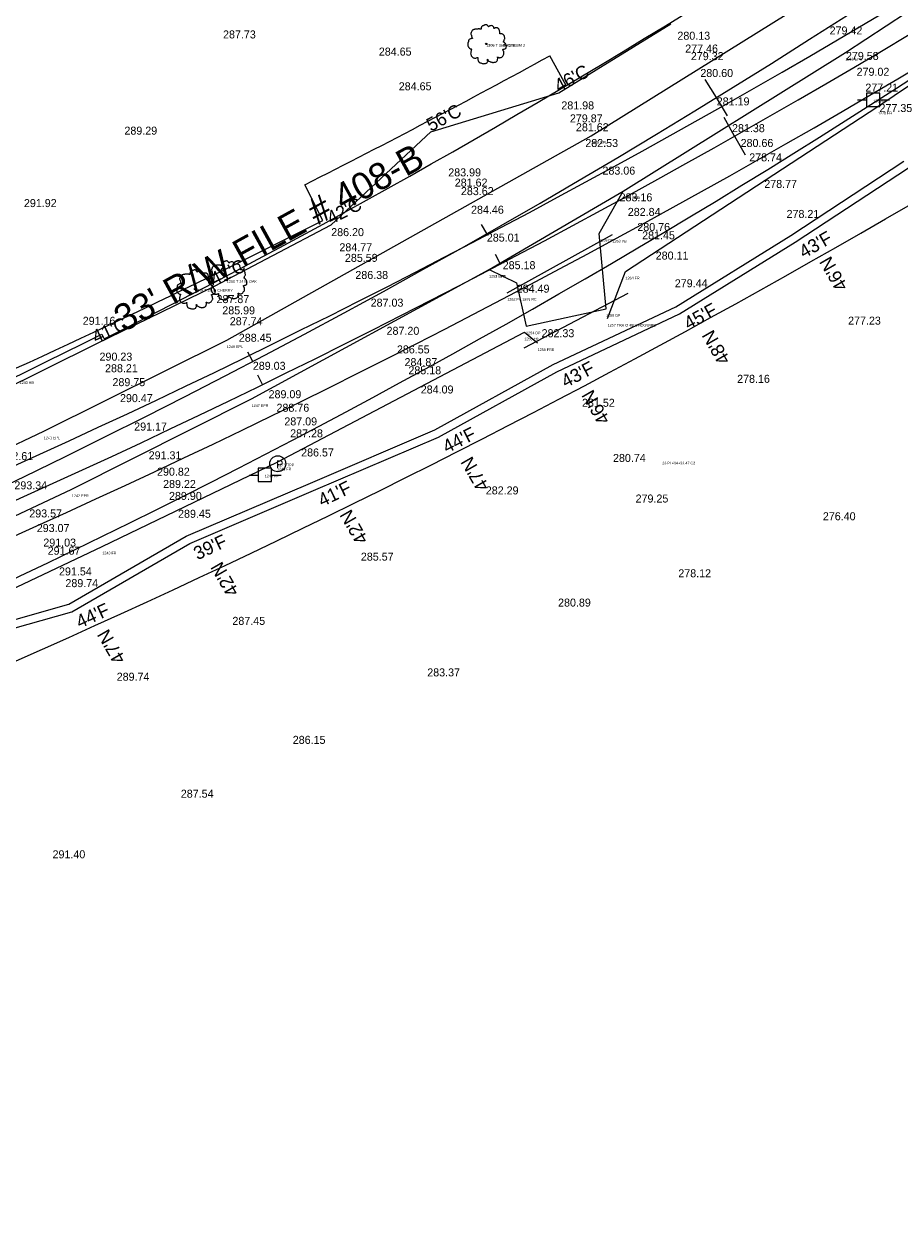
# Model space of a CAD drawing. Extents: x 49683 to 58852, y 49525 to 54803.
# Drawn here: x 51884.7 to 52213, y 49959.7 to 50412.9 of the extents above; entities that cross this region are included whole.
import ezdxf

# ---------------------------------------------------------------- set-up
doc = ezdxf.new("R2010")
doc.units = 0
for name, color, linetype in [('Level 1', 7, 'Continuous'), ('Level 11', 7, 'Continuous'), ('Level 13', 7, 'Continuous'), ('Level 18', 7, 'Continuous'), ('Level 19', 7, 'Continuous'), ('Level 20', 7, 'Continuous'), ('Level 25', 7, 'Continuous'), ('Level 3', 7, 'Continuous'), ('Level 32', 7, 'Continuous'), ('Level 33', 7, 'Continuous'), ('Level 34', 7, 'Continuous'), ('Level 48', 7, 'Continuous'), ('Level 51', 7, 'Continuous'), ('Level 53', 7, 'Continuous'), ('Level 56', 7, 'Continuous'), ('Level 58', 7, 'Continuous'), ('Level 59', 7, 'Continuous'), ('Level 6', 7, 'Continuous'), ('Level 61', 7, 'Continuous'), ('Level 8', 7, 'Continuous'), ('Level 9', 7, 'Continuous')]:
    doc.layers.add(name, color=color, linetype=linetype)

# ---------------------------------------------------------------- blocks, each defined once
blk = doc.blocks.new('PP')
at = {"layer": 'Level 9'}
for p, q in [((2.53, 2.45), (-2.47, 2.45)), ((-2.47, 2.45), (-2.47, -2.55)), ((2.53, -2.55), (2.53, 2.45)), ((-5.91, -0.11), (-2.44, -0.11)), ((-2.47, -2.55), (2.53, -2.55)), ((2.45, -0.11), (6.09, -0.11))]:
    blk.add_line(p, q, dxfattribs=at)
blk = doc.blocks.new('TPP')
at = {"layer": 'Level 9'}
blk.add_circle((0, 0), 3, dxfattribs=at)
blk.add_text('P', height=3, dxfattribs=at).set_placement((-0.59, -1.73))
blk = doc.blocks.new('T1')
at = {"layer": 'Level 11'}
for centre, radius in [((0, 0), 0.25), ((-0.01, -0.02), 0.0001)]:
    blk.add_circle(centre, radius, dxfattribs=at)
for points in [[(0.13, 7.17), (-0.17, 7.19), (-0.49, 7.09), (-0.74, 6.99), (-0.97, 6.92), (-1.19, 6.82), (-1.49, 6.64), (-1.72, 6.44), (-1.84, 6.19), (-1.89, 5.97), (-1.94, 5.69), (-1.94, 5.52), (-2.07, 5.49), (-2.22, 5.52), (-2.47, 5.59), (-2.72, 5.59), (-2.97, 5.59), (-3.32, 5.57), (-3.67, 5.57), (-3.94, 5.52), (-4.27, 5.47), (-4.64, 5.34), (-4.99, 5.22), (-5.29, 4.97), (-5.54, 4.49), (-5.67, 4.14), (-5.82, 3.89), (-5.67, 3.44), (-5.49, 3.09), (-5.47, 2.89), (-5.39, 2.47), (-5.29, 2.24), (-5.17, 2.04), (-5.24, 2.02), (-5.62, 1.97), (-5.92, 1.87), (-6.34, 1.64), (-6.57, 1.42), (-6.67, 1.09), (-6.69, 0.75), (-6.79, 0.55), (-6.87, 0.27), (-6.89, 0.2), (-6.94, -0.13), (-6.84, -0.58), (-6.82, -0.93), (-6.69, -1.15), (-6.54, -1.33), (-6.37, -1.58), (-5.97, -1.8), (-5.64, -1.9), (-5.44, -1.93), (-5.62, -2.43), (-5.67, -2.78), (-5.79, -3.18), (-5.79, -3.25), (-5.84, -3.73), (-5.69, -4.05), (-5.62, -4.43), (-5.44, -4.65), (-5.17, -4.95), (-4.84, -5.18), (-4.34, -5.3), (-3.94, -5.28), (-3.37, -5.1), (-3.12, -5.03), (-3.14, -5.2), (-3.12, -5.58), (-3.12, -6), (-2.97, -6.33), (-2.87, -6.6), (-2.72, -6.85), (-2.39, -7.08), (-1.99, -7.15), (-1.57, -7.3), (-1.12, -7.38), (-0.62, -7.4), (-0.02, -7.25), (0.26, -7.13), (0.36, -6.95), (0.56, -6.58), (0.51, -6.35), (0.53, -5.75), (0.63, -5.93), (0.81, -6.28), (1.31, -6.58), (1.71, -6.75), (2.18, -6.9), (2.48, -6.98), (2.96, -6.9), (3.33, -6.83), (3.71, -6.7), (4.01, -6.43), (4.18, -6.15), (4.23, -5.88), (4.31, -5.5), (4.36, -5.33)], [(4.36, -5.33), (4.28, -5.15), (4.23, -4.9), (4.31, -4.93), (4.48, -4.98), (4.75, -5.1), (4.98, -5.18), (5.3, -5.15), (5.58, -5.05), (6.03, -4.78), (6.3, -4.3), (6.58, -3.9), (6.65, -3.58), (6.6, -3.35), (6.58, -2.85), (6.38, -2.6), (6.33, -2.48), (6.23, -2.08), (6.3, -2.03), (6.58, -1.98), (6.95, -1.85), (7.23, -1.73), (7.45, -1.55), (7.53, -1.33), (7.5, -0.93), (7.55, -0.53), (7.48, -0.38), (7.38, -0.23), (7.3, -0.03), (7.15, 0.12), (7.05, 0.27), (6.95, 0.37), (6.83, 0.52), (6.65, 0.65), (6.5, 0.7), (6.45, 0.85), (6.6, 1.04), (6.65, 1.14), (6.68, 1.37), (6.9, 1.72), (6.95, 2.12), (6.9, 2.54), (6.85, 2.82), (6.7, 3.09), (6.5, 3.34), (6.38, 3.52), (6.2, 3.64), (5.88, 3.77), (5.63, 3.82), (5.28, 3.82), (5.08, 3.87), (5.1, 3.92), (5.1, 4.07), (5.1, 4.34), (5.03, 4.79), (4.88, 5.29), (4.88, 5.32), (4.78, 5.57), (4.56, 5.77), (4.38, 5.87), (4.18, 5.99), (3.93, 6.02), (3.63, 6.02), (3.36, 5.97), (3.16, 5.87), (2.98, 5.74), (2.91, 5.89), (2.81, 6.19), (2.76, 6.34), (2.61, 6.52), (2.38, 6.72), (1.93, 6.84), (1.31, 6.77), (1.01, 6.57), (0.86, 6.39), (0.81, 6.52), (0.61, 6.72), (0.51, 6.89), (0.33, 7.02), (0.18, 7.12), (0.08, 7.17)]]:
    blk.add_spline(points, degree=3, dxfattribs=at)

msp = doc.modelspace()

# ---------------------------------------------------------------- linework, layer by layer
at = {"layer": 'Level 1'}
for p, q in [((52144.23, 50385.43), (52140.03, 50392.24)), ((52148.42, 50378.61), (52144.23, 50385.43)), ((52058.19, 50334.47), (52056.21, 50337.95)), ((51970.43, 50286.55), (51968.57, 50290.09))]:
    msp.add_line(p, q, dxfattribs=at)
msp.add_arc((50641.56, 52824.47), 2864.78, 268.37962, 311.63333, dxfattribs=at)
at = {"layer": 'Level 13'}
msp.add_line((51913.82, 50296.82), (51914.71, 50295.04), dxfattribs=at)
for radius, start, end in [(2897.79, 282.71776, 311.63339), (2831.79, 296.71776, 308.71775), (2829.79, 291.71776, 296.71776)]:
    msp.add_arc((50641.55, 52824.48), radius, start, end, dxfattribs=at)
at = {"layer": 'Level 18'}
for p, q in [((52085.2, 50387.24), (52127.19, 50413.14)), ((52037.2, 50372.6), (52085.2, 50387.24)), ((51999.77, 50337.74), (52037.2, 50372.6)), ((52172.09, 50333.76), (52214.48, 50361.59)), ((52173.7, 50331.23), (52216.16, 50359.11)), ((51956.06, 50314.79), (51999.77, 50337.74)), ((52128.98, 50307.02), (52172.09, 50333.76)), ((52130.41, 50304.38), (52173.7, 50331.23)), ((51911.67, 50293.16), (51956.06, 50314.79)), ((52083.08, 50285.4), (52128.98, 50307.02)), ((52084.44, 50282.72), (52130.41, 50304.38)), ((51867.42, 50271.18), (51911.67, 50293.16)), ((52038.68, 50260.96), (52083.08, 50285.4)), ((52040, 50258.26), (52084.44, 50282.72)), ((51992.06, 50240.96), (52038.68, 50260.96)), ((51993.24, 50238.2), (52040, 50258.26)), ((51945.46, 50221.09), (51992.06, 50240.96)), ((51946.81, 50218.4), (51993.24, 50238.2)), ((51901.47, 50195.57), (51945.46, 50221.09)), ((51902.65, 50192.79), (51946.81, 50218.4)), ((51852.29, 50181.64), (51901.47, 50195.57)), ((51853.33, 50178.82), (51902.65, 50192.79))]:
    msp.add_line(p, q, dxfattribs=at)
at = {"layer": 'Level 19'}
for p, q in [((52151.03, 50370.99), (52147.09, 50377.95)), ((52151.03, 50370.99), (52154.97, 50364.02)), ((52063.25, 50323.09), (52061.39, 50326.63)), ((51974.05, 50277.89), (51972.3, 50281.49))]:
    msp.add_line(p, q, dxfattribs=at)
msp.add_arc((50539, 53220.69), 3274.06, 284.51284, 311.63337, dxfattribs=at)
at = {"layer": 'Level 20'}
for radius in [3262.06, 3286.06]:
    msp.add_arc((50539, 53220.69), radius, 284.51246, 311.63318, dxfattribs=at)
at = {"layer": 'Level 3'}
for p, q in [((52192.62, 50402.34), (52274.71, 50456.75)), ((52097.21, 50371.15), (52176.97, 50420.76)), ((52109.21, 50350.41), (52192.62, 50402.34)), ((51960.69, 50294.57), (52097.21, 50371.15)), ((52059, 50320.98), (52109.21, 50350.41)), ((51969.98, 50272.55), (52059, 50320.98)), ((51892.1, 50260.44), (51960.69, 50294.57)), ((51902.62, 50238.73), (51969.98, 50272.55)), ((51826.71, 50229.65), (51892.1, 50260.44)), ((51834.95, 50207.07), (51902.62, 50238.73))]:
    msp.add_line(p, q, dxfattribs=at)
at = {"layer": 'Level 33'}
for p, q in [((52087.91, 50389.92), (52081.78, 50401.12)), ((51996.68, 50339.38), (51989.91, 50352.76))]:
    msp.add_line(p, q, dxfattribs=at)
for radius, start, end in [(3329.06, 284.51246, 308.24612), (3214.06, 296.83528, 298.68607), (3229.06, 290.80829, 296.83528)]:
    msp.add_arc((50539, 53220.69), radius, start, end, dxfattribs=at)
at = {"layer": 'Level 34'}
msp.add_line((52072.19, 50291.63), (52111.15, 50312.1), dxfattribs=at)
at = {"layer": 'Level 6'}
msp.add_line((52065.82, 50312.34), (52105.27, 50334.14), dxfattribs=at)
at = {"layer": 'Level 8'}
for p, q in [((52204.78, 50382.12), (52286.9, 50437.81)), ((52110.13, 50320.32), (52204.78, 50382.12)), ((52100.29, 50334.5), (52109.21, 50350.41)), ((52102.84, 50306.33), (52100.29, 50334.5)), ((52059, 50320.98), (52069.29, 50316.04)), ((52069.29, 50316.04), (52072.89, 50299.75)), ((52103.43, 50302.65), (52110.13, 50320.32)), ((52072.89, 50299.75), (52102.84, 50306.33)), ((51979.55, 50248.78), (52072.23, 50297.54)), ((52072.23, 50297.54), (52077.21, 50293.52)), ((51914.03, 50217.29), (51979.55, 50248.78)), ((51843.63, 50183.86), (51914.03, 50217.29))]:
    msp.add_line(p, q, dxfattribs=at)

# ---------------------------------------------------------------- block references
at = {"layer": 'Level 11'}
for p in [(52057.94, 50405.56), (51948.78, 50313.69), (51960.7, 50317.06)]:
    msp.add_blockref('T1', p, dxfattribs=at)
at = {"layer": 'Level 9'}
for name, p in [('PP', (52203, 50384.66)), ('TPP', (51979.81, 50248.25)), ('PP', (51974.93, 50244.12))]:
    msp.add_blockref(name, p, dxfattribs=at)

# ---------------------------------------------------------------- texts
at = {"layer": 'Level 25'}
msp.add_text("33' R/W FILE # 408-B", height=10, rotation=28.841, dxfattribs=at).set_placement((51922, 50297.4))
at = {"layer": 'Level 32'}
for s, p in [('279.42', (52186.65, 50409.09)), ('287.73', (51959.29, 50407.61)), ('280.13', (52129.6, 50407.13)), ('284.65', (52017.68, 50401.18)), ('277.46', (52132.53, 50402.32)), ('279.32', (52134.64, 50399.48)), ('279.58', (52192.77, 50399.55)), ('280.60', (52138.2, 50393.15)), ('279.02', (52196.77, 50393.62)), ('284.65', (52025.15, 50388.18)), ('277.21', (52200.05, 50387.68)), ('281.98', (52086.1, 50381.02)), ('281.19', (52144.34, 50382.52)), ('277.35', (52205.36, 50380.03)), ('279.87', (52089.3, 50376.15)), ('281.62', (52091.56, 50372.84)), ('281.38', (52150.07, 50372.49)), ('289.29', (51922.32, 50371.56)), ('282.53', (52095.08, 50366.91)), ('280.66', (52153.29, 50366.94)), ('278.74', (52156.52, 50361.55)), ('283.99', (52043.71, 50355.92)), ('283.06', (52101.51, 50356.58)), ('281.62', (52046.14, 50352.1)), ('278.77', (52162.17, 50351.6)), ('283.62', (52048.45, 50348.9)), ('283.16', (52107.93, 50346.57)), ('291.92', (51884.65, 50344.42)), ('284.46', (52052.25, 50341.93)), ('282.84', (52111, 50341.11)), ('278.21', (52170.52, 50340.35)), ('286.20', (51999.83, 50333.53)), ('285.01', (52058.17, 50331.48)), ('280.76', (52114.58, 50335.45)), ('281.45', (52116.38, 50332.35)), ('284.77', (52002.9, 50327.86)), ('285.59', (52004.97, 50323.89)), ('280.11', (52121.47, 50324.75)), ('285.18', (52064.11, 50321.15)), ('286.38', (52008.88, 50317.48)), ('279.44', (52128.62, 50314.36)), ('284.49', (52069.37, 50312.34)), ('287.87', (51956.84, 50308.44)), ('285.99', (51959, 50304.22)), ('287.03', (52014.61, 50307.11)), ('291.16', (51906.69, 50300.31)), ('287.74', (51961.81, 50300.15)), ('277.23', (52193.58, 50300.37)), ('287.20', (52020.58, 50296.56)), ('282.33', (52078.69, 50295.66)), ('288.45', (51965.2, 50293.96)), ('290.23', (51912.99, 50286.87)), ('286.55', (52024.45, 50289.58)), ('288.21', (51915.06, 50282.53)), ('289.03', (51970.45, 50283.44)), ('284.87', (52027.31, 50284.82)), ('285.18', (52028.77, 50281.76)), ('289.75', (51917.84, 50277.32)), ('278.16', (52151.99, 50278.56)), ('289.09', (51976.36, 50272.8)), ('284.09', (52033.4, 50274.57)), ('290.47', (51920.66, 50271.33)), ('288.76', (51979.33, 50267.73)), ('281.52', (52093.84, 50269.59)), ('291.17', (51925.99, 50260.69)), ('287.09', (51982.26, 50262.61)), ('287.28', (51984.45, 50258.13)), ('292.61', (51875.85, 50249.6)), ('291.31', (51931.41, 50249.91)), ('286.57', (51988.56, 50250.97)), ('280.74', (52105.46, 50248.92)), ('290.82', (51934.55, 50243.76)), ('293.34', (51881.08, 50238.66)), ('289.22', (51936.82, 50239.17)), ('282.29', (52057.78, 50236.75)), ('289.90', (51939.03, 50234.69)), ('279.25', (52113.93, 50233.71)), ('293.57', (51886.66, 50228.13)), ('289.45', (51942.43, 50228)), ('276.40', (52184.12, 50227.06)), ('293.07', (51889.46, 50222.65)), ('291.03', (51891.91, 50217.21)), ('291.67', (51893.55, 50214.15)), ('285.57', (52010.95, 50211.93)), ('291.54', (51897.8, 50206.4)), ('278.12', (52129.94, 50205.7)), ('289.74', (51900.2, 50202.01)), ('280.89', (52084.87, 50194.72)), ('287.45', (51962.79, 50187.87)), ('283.37', (52035.83, 50168.56)), ('289.74', (51919.43, 50166.94)), ('286.15', (51985.42, 50143.28)), ('287.54', (51943.46, 50123.1)), ('291.40', (51895.38, 50100.39))]:
    msp.add_text(s, height=3, dxfattribs=at).set_placement(p)
at = {"layer": 'Level 48'}
for s, rotation, p in [("46'C", 28.6211, (52085.2, 50387.24)), ("56'C", 27.7462, (52037.2, 50372.6)), ("42'C", 26.8711, (51999.77, 50337.74)), ("43'F", 29.4962, (52177.01, 50325.05)), ("46'N", 119.917, (52193.67, 50314.71)), ("41'C", 25.9962, (51956.06, 50314.79)), ("45'F", 28.6212, (52133.77, 50298.24)), ("41'C", 25.1212, (51911.67, 50293.16)), ("48'N", 119.917, (52149.63, 50287.13)), ("43'F", 27.7461, (52087.73, 50276.55)), ("46'N", 119.917, (52104.55, 50264.71)), ("44'F", 26.8712, (52043.2, 50252.04)), ("47'N", 119.917, (52059.22, 50239.7)), ("41'F", 25.9962, (51996.44, 50231.97)), ("42'N", 119.917, (52013.88, 50219.85)), ("39'F", 25.1212, (51949.71, 50212.03)), ("42'N", 119.917, (51965.46, 50200.26)), ("44'F", 24.2462, (51905.58, 50186.45)), ("47'N", 119.917, (51922.96, 50175))]:
    msp.add_text(s, height=5, rotation=rotation, dxfattribs=at).set_placement(p)
at = {"layer": 'Level 51'}
msp.add_text('23 PI 494+33.47 C2', height=1, dxfattribs=at).set_placement((52123.93, 50247.98))
at = {"layer": 'Level 53'}
for s, p in [('1268 EPR', (52192.62, 50399.34)), ('1265 EPL', (52097.21, 50368.15)), ('1261 EPR', (52109.21, 50347.41)), ('1251 EPR', (52059, 50317.98)), ('1248 EPL', (51960.69, 50291.57)), ('1247 EPR', (51969.98, 50269.55)), ('1241 EPL', (51892.1, 50257.44)), ('1242 EPR', (51902.62, 50235.73))]:
    msp.add_text(s, height=1, dxfattribs=at).set_placement(p)
at = {"layer": 'Level 56'}
for s, p in [('1263 PB', (52105.27, 50331.14)), ('1262 PA 18IN RC', (52065.82, 50309.34))]:
    msp.add_text(s, height=1, dxfattribs=at).set_placement(p)
at = {"layer": 'Level 58'}
for s, p in [('1270 FR', (52204.78, 50379.12)), ('1260 DPB', (52109.21, 50347.41)), ('1259 DP', (52100.29, 50331.5)), ('1252 DPA', (52059, 50317.98)), ('1264 FR', (52110.13, 50317.32)), ('1253 DP', (52069.29, 50313.04)), ('1258 DP', (52102.84, 50303.33)), ('1257 FRA O 48IN HOGWIRE', (52103.43, 50299.65)), ('1255 FR', (52072.23, 50294.54)), ('1254 DP', (52072.89, 50296.75)), ('1256 FRB', (52077.21, 50290.52)), ('1246 FR', (51979.55, 50245.78)), ('1243 FR', (51914.03, 50214.29))]:
    msp.add_text(s, height=1, dxfattribs=at).set_placement(p)
at = {"layer": 'Level 59'}
for s, p in [('1269 PP', (52203, 50383.66)), ('1245 TPP', (51979.81, 50247.25)), ('1244 PP', (51974.93, 50243.12))]:
    msp.add_text(s, height=1, dxfattribs=at).set_placement(p)
at = {"layer": 'Level 61'}
for s, p in [('1266 T 36 IN OAK', (52057.94, 50404.56)), ('1709 T 36IN OAK BM 3', (52057.94, 50404.56)), ('1250 T 24 IN OAK', (51960.7, 50316.06)), ('1249 T 18 IN CHERRY', (51948.78, 50312.69)), ('1240 HB', (51883, 50278.13))]:
    msp.add_text(s, height=1, dxfattribs=at).set_placement(p)

doc.saveas('drawing.dxf')
